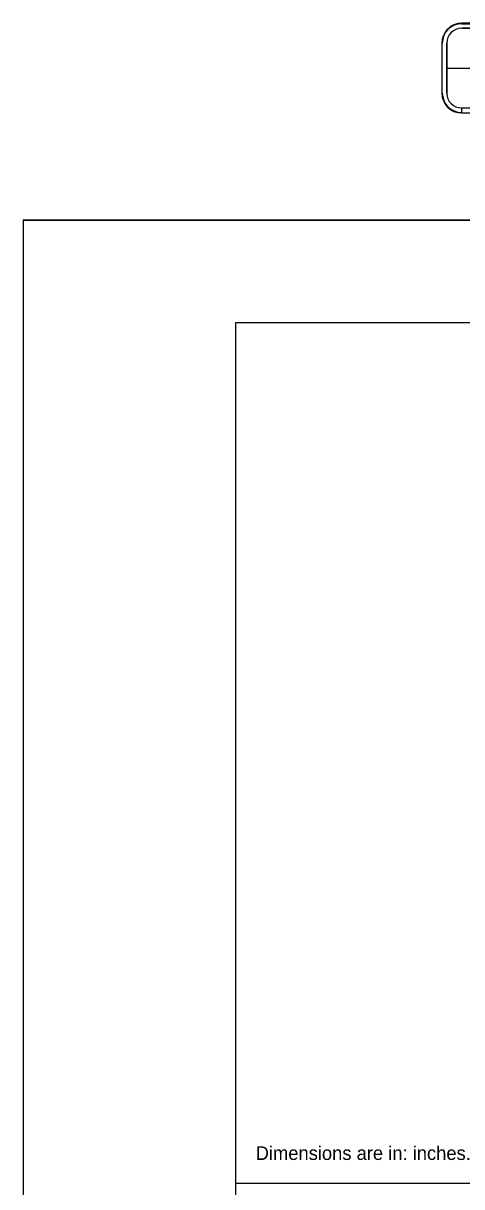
# Model space of a CAD drawing. Extents: x 2149961 to 2150220, y 145114 to 145240.
# Drawn here: x 2150010.46 to 2150025.13, y 145187.59 to 145226.53 of the extents above; entities that cross this region are included whole.
import ezdxf

# ---------------------------------------------------------------- set-up
doc = ezdxf.new("R2010")
doc.units = 0
for name, color, linetype in [('BORDER', 7, 'Continuous'), ('GSBWFILL', 7, 'Continuous'), ('GSCOLORFILL', 7, 'Continuous'), ('GSOUTLINE', 7, 'Continuous'), ('Level 1', 7, 'Continuous'), ('NON-PLOT', 7, 'Continuous'), ('PDF', 7, 'Continuous')]:
    doc.layers.add(name, color=color, linetype=linetype)

msp = doc.modelspace()

# ---------------------------------------------------------------- linework, layer by layer
at = {"layer": 'BORDER'}
for p, q in [((2150010.458, 145219.948), (2150174.061, 145219.948)), ((2150010.458, 145219.948), (2150010.458, 145114.088)), ((2150171.536, 145216.512), (2150017.557, 145216.512)), ((2150017.557, 145216.512), (2150017.557, 145117.388))]:
    msp.add_line(p, q, dxfattribs=at)
at = {"layer": 'GSBWFILL'}
for p, q in [((2150036.797, 145226.535), (2150025.13, 145226.535)), ((2150025.13, 145226.368), (2150036.797, 145226.368)), ((2150024.463, 145225.868), (2150024.463, 145224.2)), ((2150024.63, 145224.2), (2150024.63, 145225.868)), ((2150025.13, 145223.534), (2150025.13, 145223.7))]:
    msp.add_line(p, q, dxfattribs=at)
for centre, radius, start, end in [((2150025.13, 145225.868), 0.667, 90, 180), ((2150025.13, 145225.868), 0.5, 90, 180), ((2150025.13, 145224.2), 0.667, 180, 270), ((2150025.13, 145224.2), 0.5, 180, 270)]:
    msp.add_arc(centre, radius, start, end, dxfattribs=at)
at = {"layer": 'GSCOLORFILL'}
for p, q in [((2150036.797, 145226.535), (2150025.13, 145226.535)), ((2150036.797, 145226.535), (2150025.13, 145226.535)), ((2150036.797, 145226.535), (2150025.13, 145226.535)), ((2150025.13, 145226.518), (2150036.797, 145226.518)), ((2150025.13, 145226.368), (2150036.797, 145226.368)), ((2150024.463, 145225.868), (2150024.463, 145224.2)), ((2150024.463, 145225.868), (2150024.463, 145224.2)), ((2150024.463, 145225.868), (2150024.463, 145224.2)), ((2150024.48, 145224.2), (2150024.48, 145225.868)), ((2150024.63, 145224.2), (2150024.63, 145225.868)), ((2150025.13, 145223.534), (2150025.13, 145223.7)), ((2150025.13, 145223.534), (2150025.13, 145223.55)), ((2150025.13, 145223.534), (2150036.797, 145223.534))]:
    msp.add_line(p, q, dxfattribs=at)
for centre, radius, start, end in [((2150025.13, 145225.868), 0.667, 90, 180), ((2150025.13, 145225.868), 0.667, 90, 180), ((2150025.13, 145225.868), 0.667, 90, 180), ((2150025.13, 145225.868), 0.65, 90, 180), ((2150025.13, 145225.868), 0.5, 90, 180), ((2150025.13, 145224.2), 0.667, 180, 270), ((2150025.13, 145224.2), 0.667, 180, 270), ((2150025.13, 145224.2), 0.667, 180, 270), ((2150025.13, 145224.2), 0.65, 180, 270), ((2150025.13, 145224.2), 0.5, 180, 270)]:
    msp.add_arc(centre, radius, start, end, dxfattribs=at)
at = {"layer": 'GSOUTLINE'}
for p, q in [((2150036.797, 145226.535), (2150025.13, 145226.535)), ((2150036.797, 145226.368), (2150025.13, 145226.368)), ((2150024.463, 145225.868), (2150024.463, 145224.2)), ((2150024.63, 145225.868), (2150024.63, 145224.2)), ((2150025.13, 145223.7), (2150036.797, 145223.7)), ((2150025.13, 145223.534), (2150036.797, 145223.534))]:
    msp.add_line(p, q, dxfattribs=at)
for centre, radius, start, end in [((2150025.13, 145225.868), 0.667, 90, 180), ((2150025.13, 145225.868), 0.5, 90, 180), ((2150025.13, 145224.2), 0.667, 180, 270), ((2150025.13, 145224.2), 0.5, 180, 270)]:
    msp.add_arc(centre, radius, start, end, dxfattribs=at)
at = {"layer": 'Level 1'}
msp.add_line((2150017.557, 145187.705), (2150062.583, 145187.705), dxfattribs=at)
at = {"layer": 'NON-PLOT'}
msp.add_line((2150024.63, 145225.034), (2150025.713, 145225.034), dxfattribs=at)
at = {"layer": 'PDF'}
msp.add_lwpolyline([(2150010.458, 145114.088), (2150174.061, 145114.088), (2150174.061, 145219.948), (2150010.458, 145219.948)], close=True, dxfattribs=at)

# ---------------------------------------------------------------- texts
at = {"layer": 'Level 1'}
msp.add_text('Dimensions are in: inches.tenths', height=0.45913, dxfattribs=at).set_placement((2150018.235, 145188.484))

doc.saveas('drawing.dxf')
